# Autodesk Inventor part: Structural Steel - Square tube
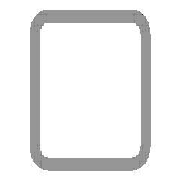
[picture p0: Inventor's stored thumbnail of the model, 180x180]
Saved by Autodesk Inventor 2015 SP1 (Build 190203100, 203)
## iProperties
IsCustomPart: 1
Created: 2011-06
Part Number: Structural Steel - Square tube
Material: Stainless Steel
Document SubType Name: Modeling
Standard: ISO
Designer: Guilherme Augusto Franco de Souza
Standard Revision: Second edition 2001-09-01
Standards Organization: ISO
Language: en-US
Size Designation: 25x25x2
Categories: <MemberInstance><Categories><Category DisplayName="Structural Shapes" InternalName="089c4875-fa83-4c05-b084-43b9cc11f5ed" Mnemonic="GRDR"><CategoryParameter Dis
Stock Number: 25x25x2
Density: 8.08 g/cm^3
Description: ISO 4019 - 25x25x2
Appearance: Steel
G_L: 700,000 mm
G_W: 25,000 mm
G_H: 25,000 mm
+0F80EDEF-A486-4730-8E53-CB40EEA5F8AB+CUTDETAIL1: Miter 45,00 deg
+B56EE3C7-5F2D-4B34-8060-3F06F4014C4C+CUTDETAIL2: Miter 45,00 deg
Author: Guilherme Augusto Franco de Souza
_CCFamilyMember: 2
_CCFamilyDisplayName: ISO 4019 (Square) - Structural steels - Cold-formed, welded, structural hollow sections
_FrameMemberDoc: Frame Member File
_Version: 15.0.0
_GetPNFromCC: 1
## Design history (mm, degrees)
node "Start plane"
node "End plane"
sketch "Sketch"
  geometry: L1 (-12.5, -8.5)-(-12.5, 8.5); L2 (-8.5, 12.5)-(8.5, 12.5); L3 (12.5, 8.5)-(12.5, -8.5); L4 (8.5, -12.5)-(-8.5, -12.5); L5 (-8.5, 10.5)-(8.5, 10.5); L6 (10.5, 8.5)-(10.5, -8.5); L7 (8.5, -10.5)-(-8.5, -10.5); L8 (-10.5, -8.5)-(-10.5, 8.5); L9 (0, 18.66)-(0, -18.66) reference; L10 (-18.66, 0)-(18.66, 0) reference; A1 r 4 centre (-8.5, -8.5) between (-12.5, -8.5) and (-8.5, -12.5); A2 r 4 centre (8.5, 8.5) between (12.5, 8.5) and (8.5, 12.5); A3 r 4 centre (-8.5, 8.5) between (-8.5, 12.5) and (-12.5, 8.5); A4 r 4 centre (8.5, -8.5) between (8.5, -12.5) and (12.5, -8.5); A5 r 2 centre (-8.5, 8.5) between (-8.5, 10.5) and (-10.5, 8.5); A6 r 2 centre (8.5, 8.5) between (10.5, 8.5) and (8.5, 10.5); A7 r 2 centre (8.5, -8.5) between (8.5, -10.5) and (10.5, -8.5); A8 r 2 centre (-8.5, -8.5) between (-10.5, -8.5) and (-8.5, -10.5)
  constraints: 16 end point, 16 point on circle, 8 centre point, 8 tangent, 4 parallel, 3 equal radius, 2 perpendicular, 7 other
  dimensions: "d7" = 4 radius of A1 (= G_IR); "d9" = 25 distance between parallel lines of L1 L3 (= G_W); "d11" = 25 distance between parallel lines of L2 L4 (= G_H); "d12" = 2 distance between parallel lines of L3 L6 (= G_T); "d15" = 12.5 distance between parallel lines of L9 L3 (= 0.5 x d9); "d16" = 12.5 distance between parallel lines of L2 L10 (= 0.5 x d11)
extrude "Body" new body sketch "Sketch" stored distance "d3" = 700 (= G_L); taper "d4" = 0 deg
node "Driven Length"
  sketch "Sketch3"
    geometry: L1 (0, 0)-(10, 0) reference
    constraints: 2 end point, 1 horizontal
  workplane "Work Plane3"
  sketch "Sketch4"
    geometry: L1 (-2, 0.141)-(12, 0.141) reference; L2 (-2, 699.859)-(12, 699.859) reference
    dimensions: "d18" = 699.71716 distance between parallel lines of L1 L2 (derived)
workplane "Work Plane4"
split "Split1"
workplane "Work Plane5"
split "Split2"
body "Solid1"
other parameters: "G_W" = 25 [user parameter; used in 1 equation term], "G_H" = 25 [user parameter; used in 1 equation term], "G_T" = 2 [user parameter; used in 1 equation term], "G_IR" = 4 [user parameter; used in 1 equation term], "G_L" = 700 [user parameter; used in 1 equation term], "G_OFFSET_START" = -0.14142 [user parameter; used in 1 equation term], "G_OFFSET_END" = -0.14142 [user parameter; used in 1 equation term], "d13" = 0.14142 (= -G_OFFSET_START), "d14" = 699.85858 (= G_OFFSET_END + B_L), "d17" = 90 deg, "MAS" = 0.136 [user parameter]
